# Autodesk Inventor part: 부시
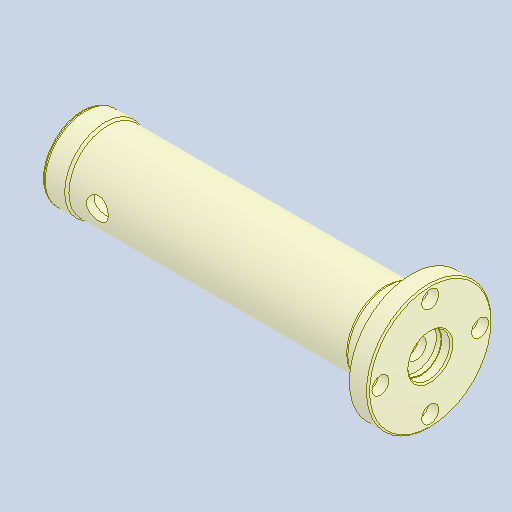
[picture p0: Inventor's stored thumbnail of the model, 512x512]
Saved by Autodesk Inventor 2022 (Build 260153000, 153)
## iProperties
Created: 2024-07
Part Number: 부시
Material: 강철, 탄소
Document SubType Name: Modeling
Designer: PC-01
Density: 7.85 g/cm^3
Appearance: 기본값
Author: jhkim
Sending System: Autodesk Inventor 2025
Preprocessor: ST-DEVELOPER v20
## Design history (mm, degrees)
feature "솔리드1"
node "솔리드2"
